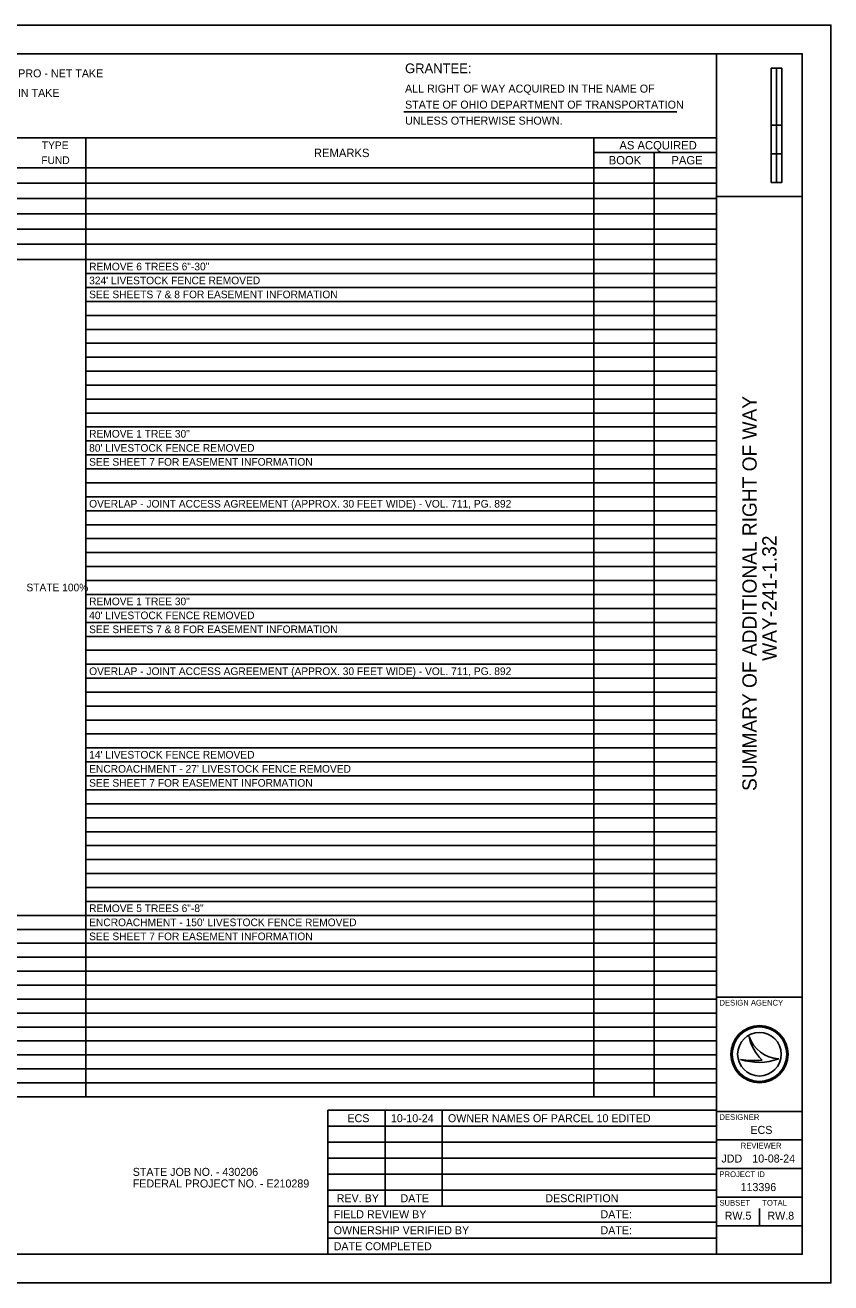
# Model space of a CAD drawing. Extents: x 0 to 34, y 0 to 22.
# Drawn here: x 19.9 to 34, y 0 to 22 of the extents above; entities that cross this region are included whole.
import ezdxf

# ---------------------------------------------------------------- set-up
doc = ezdxf.new("R2010")
doc.units = 0
for name, color, linetype in [('Default', 7, 'Continuous'), ('SH_Border', 7, 'Continuous'), ('SH_Cut_Line', 7, 'Continuous'), ('SH_Data', 7, 'Continuous'), ('SH_Text', 7, 'Continuous')]:
    doc.layers.add(name, color=color, linetype=linetype)

msp = doc.modelspace()

# ---------------------------------------------------------------- linework, layer by layer
at = {"layer": 'SH_Border'}
for p, q in [((32, 0.5), (32, 21.5)), ((32, 19), (33.5, 19)), ((32, 5), (33.5, 5)), ((32, 3), (33.5, 3)), ((32, 2.5), (33.5, 2.5)), ((32, 2), (33.5, 2)), ((32, 1.5), (33.5, 1.5)), ((32, 1), (33.5, 1))]:
    msp.add_line(p, q, dxfattribs=at)
msp.add_lwpolyline([(1.5, 21.5), (33.5, 21.5), (33.5, 0.5), (1.5, 0.5)], close=True, dxfattribs=at)
at = {"layer": 'SH_Cut_Line'}
msp.add_lwpolyline([(0, 0), (34, 0), (34, 22), (0, 22)], close=True, dxfattribs=at)
at = {"layer": 'SH_Data'}
for p, q in [((32.957, 19.25), (32.957, 21.25)), ((33.144, 21.25), (32.957, 21.25)), ((32.957, 20.25), (32.957, 21.25)), ((32.957, 21.25), (33.05, 21.25)), ((33.05, 21.25), (33.051, 21.25)), ((33.051, 21.25), (33.051, 20.25)), ((33.144, 21.25), (33.144, 19.25)), ((33.051, 20.25), (32.957, 20.25)), ((33.143, 20.25), (33.05, 20.25)), ((33.05, 20.25), (33.05, 19.75)), ((33.143, 19.75), (33.143, 20.25)), ((33.05, 19.75), (32.957, 19.75)), ((32.957, 19.75), (32.957, 19.25)), ((33.05, 19.75), (33.143, 19.75)), ((33.05, 19.25), (33.05, 19.75)), ((33.144, 19.25), (32.957, 19.25)), ((32.957, 19.25), (33.05, 19.25)), ((32.567, 4.31), (32.567, 4.31)), ((32.75, 4), (32.75, 4)), ((32.417, 3.91), (32.417, 3.91)), ((33.087, 3.919), (33.087, 3.919)), ((32.75, 1), (32.75, 1.3))]:
    msp.add_line(p, q, dxfattribs=at)
for radius in [0.5, 0.477, 0.477, 0.382]:
    msp.add_circle((32.75, 4), radius, dxfattribs=at)
for centre, radius, start, end in [((33.116, 4.498), 0.58, 198.9257, 198.9319), ((33.347, 4.47), 0.796, 191.6379, 191.6421), ((33.116, 4.498), 0.58, 198.9319, 267.1657), ((33.347, 4.47), 0.796, 191.6421, 226.0947), ((32.739, 4.87), 1.013, 251.4576, 290.0832), ((32.648, 5.154), 1.266, 259.4964, 259.4995), ((32.739, 4.87), 1.013, 251.4527, 251.4576), ((32.648, 5.154), 1.266, 259.4995, 276.6672)]:
    msp.add_arc(centre, radius, start, end, dxfattribs=at)
at = {"layer": 'SH_Text'}
for p, q in [((26.524, 20.483), (31.304, 20.483)), ((14.669, 20.027), (32, 20.027)), ((20.958, 20.027), (20.958, 18.434)), ((29.85, 20.027), (29.85, 18.434)), ((32, 20.027), (32, 18.434)), ((29.85, 19.771), (32, 19.771)), ((30.907, 19.771), (30.907, 18.434)), ((14.669, 19.504), (32, 19.504)), ((14.669, 19.237), (32, 19.237)), ((14.669, 18.969), (32, 18.969)), ((14.669, 18.702), (32, 18.702)), ((14.669, 18.434), (32, 18.434)), ((20.958, 18.434), (20.958, 18.167)), ((29.85, 18.434), (29.85, 18.167)), ((30.907, 18.434), (30.907, 18.167)), ((32, 18.434), (32, 18.167)), ((14.669, 18.167), (32, 18.167)), ((20.958, 18.167), (20.958, 17.9)), ((29.85, 18.167), (29.85, 17.9)), ((30.907, 18.167), (30.907, 17.9)), ((32, 18.167), (32, 17.9)), ((14.669, 17.9), (32, 17.9)), ((20.958, 17.9), (20.958, 15.947)), ((29.85, 17.9), (29.85, 15.947)), ((30.907, 17.9), (30.907, 15.947)), ((32, 17.9), (32, 15.947)), ((20.958, 17.656), (32, 17.656)), ((20.958, 17.412), (32, 17.412)), ((20.958, 17.168), (32, 17.168)), ((20.958, 16.923), (32, 16.923)), ((20.958, 16.679), (32, 16.679)), ((20.958, 16.435), (32, 16.435)), ((20.958, 16.191), (32, 16.191)), ((20.958, 15.947), (32, 15.947)), ((20.958, 15.947), (20.958, 15.703)), ((29.85, 15.947), (29.85, 15.703)), ((30.907, 15.947), (30.907, 15.703)), ((32, 15.947), (32, 15.703)), ((20.958, 15.703), (32, 15.703)), ((20.958, 15.703), (20.958, 15.215)), ((29.85, 15.703), (29.85, 15.215)), ((30.907, 15.703), (30.907, 15.215)), ((32, 15.703), (32, 15.215)), ((20.958, 15.459), (32, 15.459)), ((20.958, 15.215), (32, 15.215)), ((20.958, 15.215), (20.958, 14.971)), ((29.85, 15.215), (29.85, 14.971)), ((30.907, 15.215), (30.907, 14.971)), ((32, 15.215), (32, 14.971)), ((20.958, 14.971), (32, 14.971)), ((20.958, 14.971), (20.958, 14.727)), ((29.85, 14.971), (29.85, 14.727)), ((30.907, 14.971), (30.907, 14.727)), ((32, 14.971), (32, 14.727)), ((20.958, 14.727), (32, 14.727)), ((20.958, 14.727), (20.958, 14.483)), ((29.85, 14.727), (29.85, 14.483)), ((30.907, 14.727), (30.907, 14.483)), ((32, 14.727), (32, 14.483)), ((20.958, 14.483), (32, 14.483)), ((20.958, 14.483), (20.958, 10.821)), ((29.85, 14.483), (29.85, 10.821)), ((30.907, 14.483), (30.907, 10.821)), ((32, 14.483), (32, 10.821)), ((20.958, 14.238), (32, 14.238)), ((20.958, 13.994), (32, 13.994)), ((20.958, 13.75), (32, 13.75)), ((20.958, 13.506), (32, 13.506)), ((20.958, 13.262), (32, 13.262)), ((20.958, 13.018), (32, 13.018)), ((20.958, 12.774), (32, 12.774)), ((20.958, 12.53), (32, 12.53)), ((20.958, 12.286), (32, 12.286)), ((20.958, 12.042), (32, 12.042)), ((20.958, 11.797), (32, 11.797)), ((20.958, 11.553), (32, 11.553)), ((20.958, 11.309), (32, 11.309)), ((20.958, 11.065), (32, 11.065)), ((20.958, 10.821), (32, 10.821)), ((20.958, 10.821), (20.958, 10.577)), ((29.85, 10.821), (29.85, 10.577)), ((30.907, 10.821), (30.907, 10.577)), ((32, 10.821), (32, 10.577)), ((20.958, 10.577), (32, 10.577)), ((20.958, 10.577), (20.958, 10.333)), ((29.85, 10.577), (29.85, 10.333)), ((30.907, 10.577), (30.907, 10.333)), ((32, 10.577), (32, 10.333)), ((20.958, 10.333), (32, 10.333)), ((20.958, 10.333), (20.958, 9.601)), ((29.85, 10.333), (29.85, 9.601)), ((30.907, 10.333), (30.907, 9.601)), ((32, 10.333), (32, 9.601)), ((20.958, 10.089), (32, 10.089)), ((20.958, 9.845), (32, 9.845)), ((20.958, 9.601), (32, 9.601)), ((20.958, 9.601), (20.958, 9.357)), ((29.85, 9.601), (29.85, 9.357)), ((30.907, 9.601), (30.907, 9.357)), ((32, 9.601), (32, 9.357)), ((20.958, 9.357), (32, 9.357)), ((20.958, 9.357), (20.958, 9.112)), ((29.85, 9.357), (29.85, 9.112)), ((30.907, 9.357), (30.907, 9.112)), ((32, 9.357), (32, 9.112)), ((20.958, 9.112), (32, 9.112)), ((20.958, 9.112), (20.958, 8.38)), ((29.85, 9.112), (29.85, 8.38)), ((30.907, 9.112), (30.907, 8.38)), ((32, 9.112), (32, 8.38)), ((20.958, 8.868), (32, 8.868)), ((20.958, 8.624), (32, 8.624)), ((20.958, 8.38), (32, 8.38)), ((20.958, 8.38), (20.958, 8.136)), ((29.85, 8.38), (29.85, 8.136)), ((30.907, 8.38), (30.907, 8.136)), ((32, 8.38), (32, 8.136)), ((20.958, 8.136), (32, 8.136)), ((20.958, 8.136), (20.958, 7.892)), ((29.85, 8.136), (29.85, 7.892)), ((30.907, 8.136), (30.907, 7.892)), ((32, 8.136), (32, 7.892)), ((20.958, 7.892), (32, 7.892)), ((20.958, 7.892), (20.958, 3.254)), ((29.85, 7.892), (29.85, 3.254)), ((30.907, 7.892), (30.907, 3.254)), ((32, 7.892), (32, 3.254)), ((20.958, 7.648), (32, 7.648)), ((20.958, 7.404), (32, 7.404)), ((20.958, 7.16), (32, 7.16)), ((20.958, 6.916), (32, 6.916)), ((20.958, 6.672), (32, 6.672)), ((14.669, 6.427), (32, 6.427)), ((14.669, 6.183), (32, 6.183)), ((14.669, 5.939), (32, 5.939)), ((14.669, 5.695), (32, 5.695)), ((14.669, 5.451), (32, 5.451)), ((14.669, 5.207), (32, 5.207)), ((14.669, 4.963), (32, 4.963)), ((14.669, 4.719), (32, 4.719)), ((14.669, 4.475), (32, 4.475)), ((14.669, 4.231), (32, 4.231)), ((14.669, 3.987), (32, 3.987)), ((14.669, 3.742), (32, 3.742)), ((14.669, 3.498), (32, 3.498)), ((14.669, 3.254), (32, 3.254)), ((25.197, 3.02), (25.197, 0.5)), ((25.197, 3.02), (32, 3.02)), ((26.197, 3.02), (26.197, 1.34)), ((27.197, 3.02), (27.197, 1.34)), ((25.197, 2.74), (32, 2.74)), ((25.197, 2.46), (32, 2.46)), ((25.197, 2.18), (32, 2.18)), ((25.197, 1.9), (32, 1.9)), ((25.197, 1.62), (32, 1.62)), ((25.197, 1.34), (32, 1.34)), ((25.197, 1.06), (32, 1.06)), ((25.197, 0.78), (32, 0.78)), ((32, 0.5), (32, 0.5))]:
    msp.add_line(p, q, dxfattribs=at)

# ---------------------------------------------------------------- texts
at = {"layer": 'Default'}
for s, p in [('STATE JOB NO. - 430206', (21.779, 1.871)), ('FEDERAL PROJECT NO. - E210289', (21.779, 1.668))]:
    msp.add_text(s, height=0.14, dxfattribs=at).set_placement(p)
at = {"layer": 'SH_Data'}
for s, p in [('SUMMARY OF ADDITIONAL RIGHT OF WAY', (32.701, 8.604)), ('WAY-241-1.32', (33.049, 10.88))]:
    msp.add_text(s, height=0.25, rotation=90, dxfattribs=at).set_placement(p)
for s, height, p in [('DESIGN AGENCY', 0.1, (32.05, 4.85)), ('DESIGNER', 0.1, (32.05, 2.85)), ('ECS', 0.14, (32.592, 2.605)), ('REVIEWER', 0.1, (32.422, 2.35)), ('JDD', 0.14, (32.084, 2.105)), ('10-08-24', 0.14, (32.625, 2.105)), ('PROJECT ID', 0.1, (32.05, 1.85)), ('113396', 0.14, (32.419, 1.605)), ('SUBSET', 0.1, (32.05, 1.35)), ('TOTAL', 0.1, (32.8, 1.35)), ('RW.5', 0.14, (32.141, 1.105)), ('RW.8', 0.14, (32.889, 1.105))]:
    msp.add_text(s, height=height, dxfattribs=at).set_placement(p)
at = {"layer": 'SH_Text'}
for s, height, p in [('NET RESIDUE = RECORD AREA - TOTAL PRO - NET TAKE', 0.14, (16.108, 21.087)), ('GRANTEE:', 0.17, (26.546, 21.16)), ('ALL RIGHT OF WAY ACQUIRED IN THE NAME OF', 0.14, (26.546, 20.82)), ('NET TAKE = GROSS TAKE - PRO IN TAKE', 0.14, (16.799, 20.746)), ('STATE OF OHIO DEPARTMENT OF TRANSPORTATION', 0.14, (26.546, 20.54)), ('UNLESS OTHERWISE SHOWN.', 0.14, (26.546, 20.26)), ('TYPE', 0.1337, (20.188, 19.832)), ('REMARKS', 0.147, (24.951, 19.692)), ('AS ACQUIRED', 0.14704, (30.298, 19.826)), ('FUND', 0.1337, (20.179, 19.571)), ('BOOK', 0.147, (30.112, 19.564)), ('PAGE', 0.147, (31.209, 19.564)), ('REMOVE 6 TREES 6"-30"', 0.13367, (21.016, 17.711)), ("324' LIVESTOCK FENCE REMOVED", 0.13367, (21.016, 17.467)), ('SEE SHEETS 7 & 8 FOR EASEMENT INFORMATION', 0.13367, (21.016, 17.223)), ('REMOVE 1 TREE 30"', 0.13367, (21.016, 14.785)), ("80' LIVESTOCK FENCE REMOVED", 0.13367, (21.016, 14.538)), ('SEE SHEET 7 FOR EASEMENT INFORMATION', 0.13367, (21.016, 14.294)), ('OVERLAP - JOINT ACCESS AGREEMENT (APPROX. 30 FEET WIDE) - VOL. 711, PG. 892', 0.13367, (21.016, 13.561)), ('STATE 100%', 0.1337, (19.918, 12.097)), ('REMOVE 1 TREE 30"', 0.13367, (21.016, 11.853)), ("40' LIVESTOCK FENCE REMOVED", 0.13367, (21.016, 11.609)), ('SEE SHEETS 7 & 8 FOR EASEMENT INFORMATION', 0.13367, (21.016, 11.365)), ('OVERLAP - JOINT ACCESS AGREEMENT (APPROX. 30 FEET WIDE) - VOL. 711, PG. 892', 0.13367, (21.016, 10.632)), ("14' LIVESTOCK FENCE REMOVED", 0.13367, (21.016, 9.171)), ("ENCROACHMENT - 27' LIVESTOCK FENCE REMOVED", 0.13367, (21.016, 8.924)), ('SEE SHEET 7 FOR EASEMENT INFORMATION', 0.13367, (21.016, 8.679)), ('REMOVE 5 TREES 6"-8"', 0.13367, (21.016, 6.486)), ("ENCROACHMENT - 150' LIVESTOCK FENCE REMOVED", 0.13367, (21.016, 6.239)), ('SEE SHEET 7 FOR EASEMENT INFORMATION', 0.13367, (21.016, 5.994)), ('ECS', 0.14, (25.537, 2.81)), ('10-10-24', 0.14, (26.298, 2.81)), ('OWNER NAMES OF PARCEL 10 EDITED', 0.14, (27.297, 2.81)), ('REV. BY', 0.14, (25.35, 1.41)), ('DATE', 0.14, (26.466, 1.41)), ('DESCRIPTION', 0.14, (29.002, 1.41)), ('FIELD REVIEW BY', 0.14, (25.297, 1.13)), ('DATE:', 0.14, (29.967, 1.13)), ('OWNERSHIP VERIFIED BY', 0.14, (25.297, 0.85)), ('DATE:', 0.14, (29.967, 0.85)), ('DATE COMPLETED', 0.14, (25.297, 0.57))]:
    msp.add_text(s, height=height, dxfattribs=at).set_placement(p)

doc.saveas('drawing.dxf')
